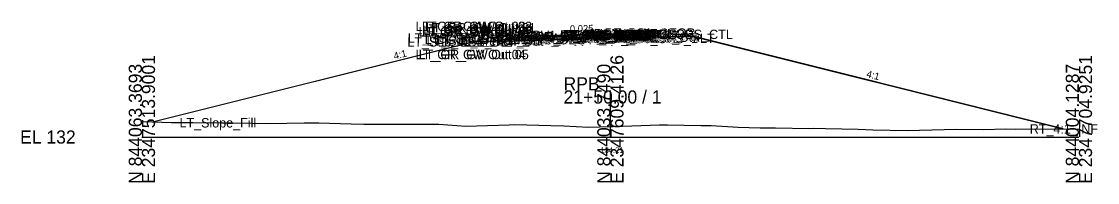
# Model space of a CAD drawing. Extents: x -76 to 2347760, y -10 to 844216.
# Drawn here: x -25.7 to 204, y 6490.3 to 6524.6 of the extents above; entities that cross this region are included whole.
import ezdxf

# ---------------------------------------------------------------- set-up
doc = ezdxf.new("R2010")
doc.units = 0
for name, color, linetype in [('Default', 7, 'Continuous'), ('Exist Cross Section Cell', 7, 'Continuous'), ('Exist XS Center Line Elevation Label', 7, 'Continuous'), ('Exist XS Ground Line', 7, 'Continuous'), ('Prop CMT Pvmt Course 1', 7, 'Continuous'), ('Prop CMT Pvmt Course 2', 7, 'Continuous'), ('Prop CMT Pvmt Course 3', 7, 'Continuous'), ('Prop CMT Pvmt Surface', 7, 'Continuous'), ('Prop CMT Pvmt Surface Shoulder', 7, 'Continuous'), ('Prop CMT Shld Paved Course 1', 7, 'Continuous'), ('Prop CMT Shld Paved Course 2', 7, 'Continuous'), ('Prop CMT Shld Paved Course 3', 7, 'Continuous'), ('Prop CMT Slope Grass', 7, 'Continuous'), ('Prop CMT Subgrade Earthwork', 7, 'Continuous'), ('Prop XS Earthwork Shape', 7, 'Continuous'), ('Prop XS SE Text', 7, 'Continuous'), ('Prop XS Side Slope Text', 7, 'Continuous'), ('Scratch_Level_0', 7, 'Continuous')]:
    doc.layers.add(name, color=color, linetype=linetype)

msp = doc.modelspace()

# ---------------------------------------------------------------- linework, layer by layer
at = {"layer": 'Exist Cross Section Cell'}
for p, q in [((100, 6500), (100, 6509.94)), ((0, 6500), (100, 6500)), ((100, 6500), (200, 6500))]:
    msp.add_line(p, q, dxfattribs=at)
at = {"layer": 'Exist XS Ground Line'}
msp.add_lwpolyline([(0, 6503.31), (4.28, 6503.19), (6.33, 6503.1), (10.88, 6503.08), (16.8, 6503.03), (19.45, 6503.01), (27.27, 6502.91), (34.63, 6503.05), (37.74, 6503.03), (44.64, 6502.82), (47.36, 6502.71), (48.21, 6502.71), (49.81, 6502.73), (58.68, 6502.74), (63.35, 6502.73), (69.15, 6502.31), (78.41, 6502.61), (79.62, 6502.64), (87.32, 6502.49), (90.09, 6502.41), (95.31, 6502.1), (100, 6502.21), (100.56, 6502.22), (110.51, 6502.61), (111.03, 6502.63), (112.17, 6502.62), (119.29, 6502.44), (121.5, 6502.42), (127.28, 6502.1), (131.97, 6501.98), (135.27, 6501.93), (142.44, 6501.82), (143.26, 6501.87), (145.93, 6501.79), (152.91, 6501.69), (156.04, 6501.56), (163.38, 6501.37), (171.22, 6501.6), (173.85, 6501.64), (179.69, 6501.62), (184.32, 6501.74), (186.4, 6501.7), (194.79, 6501.76), (200, 6501.67)], dxfattribs=at)
at = {"layer": 'Prop CMT Pvmt Course 1'}
for p, q in [((100, 6521.97), (88, 6521.67)), ((88, 6521.42), (100, 6521.72)), ((88, 6521.67), (88, 6521.42)), ((100, 6521.97), (104, 6522.07)), ((100, 6521.72), (100, 6521.97)), ((100, 6521.72), (100, 6521.97)), ((100, 6521.72), (100, 6521.84)), ((100, 6521.84), (100, 6521.84)), ((100, 6521.84), (100, 6521.72)), ((100, 6521.72), (100, 6521.84)), ((100, 6521.84), (100, 6521.84)), ((100, 6521.84), (100, 6521.72)), ((104, 6521.82), (100, 6521.72)), ((100, 6521.72), (100, 6521.72)), ((100, 6521.72), (100, 6521.72)), ((104, 6522.07), (104, 6521.82))]:
    msp.add_line(p, q, dxfattribs=at)
at = {"layer": 'Prop CMT Pvmt Course 2'}
for p, q in [((100, 6521.72), (88, 6521.42)), ((88, 6521.42), (88, 6521.08)), ((88, 6521.08), (100, 6521.38)), ((100, 6521.72), (104, 6521.82)), ((100, 6521.38), (100, 6521.72)), ((100, 6521.38), (100, 6521.72)), ((104, 6521.48), (100, 6521.38)), ((104, 6521.82), (104, 6521.48))]:
    msp.add_line(p, q, dxfattribs=at)
at = {"layer": 'Prop CMT Pvmt Course 3'}
for p, q in [((100, 6521.38), (88, 6521.08)), ((88, 6521.08), (88, 6520.75)), ((88, 6520.75), (100, 6521.05)), ((100, 6521.38), (104, 6521.48)), ((100, 6521.05), (100, 6521.38)), ((100, 6521.05), (100, 6521.38)), ((104, 6521.15), (100, 6521.05)), ((104, 6521.48), (104, 6521.15))]:
    msp.add_line(p, q, dxfattribs=at)
at = {"layer": 'Prop CMT Pvmt Surface'}
for q in [(88, 6521.67), (104, 6522.07)]:
    msp.add_line((100, 6521.97), q, dxfattribs=at)
at = {"layer": 'Prop CMT Pvmt Surface Shoulder'}
for p, q in [((88, 6521.67), (78, 6521.42)), ((104, 6522.07), (108, 6522.17))]:
    msp.add_line(p, q, dxfattribs=at)
at = {"layer": 'Prop CMT Shld Paved Course 1'}
for p, q in [((78, 6521.42), (77.74, 6521.16)), ((77.74, 6521.16), (88, 6521.42)), ((88, 6521.67), (78, 6521.42)), ((88, 6521.42), (88, 6521.67)), ((104, 6522.07), (108, 6522.17)), ((104, 6521.82), (104, 6522.07)), ((108.24, 6521.92), (104, 6521.82)), ((108, 6522.17), (108.24, 6521.92))]:
    msp.add_line(p, q, dxfattribs=at)
at = {"layer": 'Prop CMT Shld Paved Course 2'}
for p, q in [((77.74, 6521.16), (77.4, 6520.82)), ((77.4, 6520.82), (88, 6521.08)), ((88, 6521.42), (77.74, 6521.16)), ((88, 6521.08), (88, 6521.42)), ((104, 6521.82), (108.24, 6521.92)), ((104, 6521.48), (104, 6521.82)), ((108.57, 6521.6), (104, 6521.48)), ((108.24, 6521.92), (108.57, 6521.6))]:
    msp.add_line(p, q, dxfattribs=at)
at = {"layer": 'Prop CMT Shld Paved Course 3'}
for p, q in [((76.9, 6520.81), (76.56, 6520.46)), ((76.56, 6520.46), (88, 6520.75)), ((77.4, 6520.82), (76.9, 6520.81)), ((88, 6521.08), (77.4, 6520.82)), ((88, 6520.75), (88, 6521.08)), ((104, 6521.48), (108.57, 6521.6)), ((104, 6521.15), (104, 6521.48)), ((109.39, 6521.29), (104, 6521.15)), ((108.57, 6521.6), (109.07, 6521.61)), ((109.07, 6521.61), (109.39, 6521.29))]:
    msp.add_line(p, q, dxfattribs=at)
at = {"layer": 'Prop CMT Slope Grass'}
for p, q in [((74, 6521.1), (2.57, 6503.24)), ((78, 6521.42), (74, 6521.1)), ((108, 6522.17), (116, 6521.89)), ((116, 6521.89), (196.63, 6501.73))]:
    msp.add_line(p, q, dxfattribs=at)
at = {"layer": 'Prop CMT Subgrade Earthwork'}
for p, q in [((76.56, 6520.46), (70.9, 6520.32)), ((88, 6520.75), (76.56, 6520.46)), ((100, 6521.05), (88, 6520.75)), ((100, 6521.05), (104, 6521.15)), ((104, 6521.15), (117.59, 6521.49))]:
    msp.add_line(p, q, dxfattribs=at)
at = {"layer": 'Prop XS Earthwork Shape'}
msp.add_lwpolyline([(163.38, 6501.37), (171.22, 6501.6), (173.85, 6501.64), (179.69, 6501.62), (184.32, 6501.74), (186.4, 6501.7), (194.79, 6501.76), (196.63, 6501.73), (117.59, 6521.49), (104, 6521.15), (100, 6521.05), (88, 6520.75), (76.56, 6520.46), (70.9, 6520.32), (2.57, 6503.24), (4.28, 6503.19), (6.33, 6503.1), (10.88, 6503.08), (16.8, 6503.03), (19.45, 6503.01), (27.27, 6502.91), (34.63, 6503.05), (37.74, 6503.03), (44.64, 6502.82), (47.36, 6502.71), (48.21, 6502.71), (49.81, 6502.73), (58.68, 6502.74), (63.35, 6502.73), (69.15, 6502.31), (78.41, 6502.61), (79.62, 6502.64), (87.32, 6502.49), (90.09, 6502.41), (95.31, 6502.1), (100, 6502.21), (100.56, 6502.22), (110.51, 6502.61), (111.03, 6502.63), (112.17, 6502.62), (119.29, 6502.44), (121.5, 6502.42), (127.28, 6502.1), (131.97, 6501.98), (135.27, 6501.93), (142.44, 6501.82), (143.26, 6501.87), (145.93, 6501.79), (152.91, 6501.69), (156.04, 6501.56)], close=True, dxfattribs=at)

# ---------------------------------------------------------------- texts
at = {"layer": 'Default'}
msp.add_text('-', height=0.0001, dxfattribs=at).set_placement((0, 6500))
at = {"layer": 'Exist Cross Section Cell'}
for s, p in [('E 2347513.9001', (2.8, 6490)), ('N 844033.7490', (100, 6490)), ('E 2347609.4126', (102.8, 6490)), ('E 2347704.9251', (202.8, 6490)), ('N 844063.3693', (0, 6490)), ('N 844004.1287', (200, 6490))]:
    msp.add_text(s, height=2.8, rotation=90, dxfattribs=at).set_placement(p)
for s, p in [('RPB', (90, 6509.94)), ('21+50.00 / 1', (90, 6507.14)), ('EL 132', (-26, 6498.6))]:
    msp.add_text(s, height=2.8, dxfattribs=at).set_placement(p)
at = {"layer": 'Exist XS Center Line Elevation Label'}
msp.add_text('134.21', height=1.2, dxfattribs=at).set_placement((97.89, 6496.61))
at = {"layer": 'Prop XS SE Text'}
msp.add_text('0.025', height=1.5, rotation=1.4321, dxfattribs=at).set_placement((91.38, 6522.31))
at = {"layer": 'Prop XS Side Slope Text'}
for rotation, p in [(14.0362, (53.93, 6516.52)), (345.9638, (154.55, 6512.79))]:
    msp.add_text('4:1', height=1.5, rotation=rotation, dxfattribs=at).set_placement(p)
at = {"layer": 'Scratch_Level_0'}
for s, p in [('LT_GR_GW Out 03', (58.43, 6522.6)), ('LT_GR_GW Out 06', (59.05, 6521.43)), ('LT_GR_GW Out 02', (59.77, 6522.6)), ('LT_GR_GW Out 09', (59.77, 6522.01)), ('LT_GR_GW Out 07', (59.77, 6521.43)), ('LT_GR_GW Out 08', (60.04, 6521.72)), ('LT_GR_GW Out 01', (60.6, 6522.3)), ('LT_PS1_OEOP', (68.8, 6520.42)), ('LT_PV2_OEOT', (78.17, 6520.42)), ('LT_PV1_OEOT', (78.74, 6520.67)), ('RT_PV2_OEEOP', (89.26, 6520.72)), ('RT_PV3_OEEOP', (89.26, 6520.38)), ('LT_PV2_OEEOP', (89.31, 6520.72)), ('LT_PV3_OEEOP', (89.31, 6520.38)), ('RT_PV1_OEEOP', (89.83, 6520.84)), ('LT_PV1_OEEOP', (89.87, 6520.84)), ('RT_PV2_IEEOP', (89.91, 6520.72)), ('LT_PV2_IEEOP', (89.95, 6520.72)), ('RT_PV1_IEEOP', (90.47, 6520.84)), ('LT_PV1_IEEOP', (90.52, 6520.84)), ('RT_Sub_Trench_Out', (93.55, 6520.29)), ('PV2_PGL', (93.91, 6520.72)), ('RT_PV2_OEOT', (94.13, 6520.82)), ('RT_PV3_OEOT', (94.13, 6520.48)), ('PV1_PGL', (94.47, 6520.97)), ('RT_PV1_OEOT', (94.69, 6521.07)), ('RT_PS3_Shelf_Out', (95.01, 6520.61)), ('RT_PS2_OEOP', (98.43, 6520.92)), ('RT_PS1_OEOP', (98.76, 6521.17)), ('RT_PS3_OEOP', (98.76, 6520.6)), ('RT_GS_OS_CTL', (105.32, 6520.89)), ('LT_Sub_OSS_DLT', (56.67, 6519.28)), ('LT_GS_OS_GR_Face_GW', (56.75, 6520.1)), ('LT_GS_OS_CTL', (60.36, 6519.86)), ('LT_Sub_Trench_Out', (60.76, 6519.46)), ('LT_PS3_Shelf_Out', (62.89, 6519.81)), ('LT_PS3_OEOP', (67.64, 6519.82)), ('LT_PS2_OEOP', (67.98, 6520.16)), ('LT_Sub_OEOT', (78.08, 6519.75)), ('LT_PV3_OEOT', (78.17, 6520.08)), ('RT_Sub_OEEOP', (89.17, 6520.05)), ('LT_Sub_OEEOP', (89.21, 6520.05)), ('RT_Sub_OEOT', (94.03, 6520.15)), ('RT_Sub_OSS_DLT', (98.75, 6520.02)), ('LT_GR_GW Out 04', (58.43, 6516.6)), ('LT_GR_GW Out 05', (59.1, 6516.6)), ('LT_Slope_Fill', (8.03, 6502.03)), ('RT_4:1_INF', (189.51, 6500.73))]:
    msp.add_text(s, height=2, dxfattribs=at).set_placement(p)

doc.saveas('drawing.dxf')
